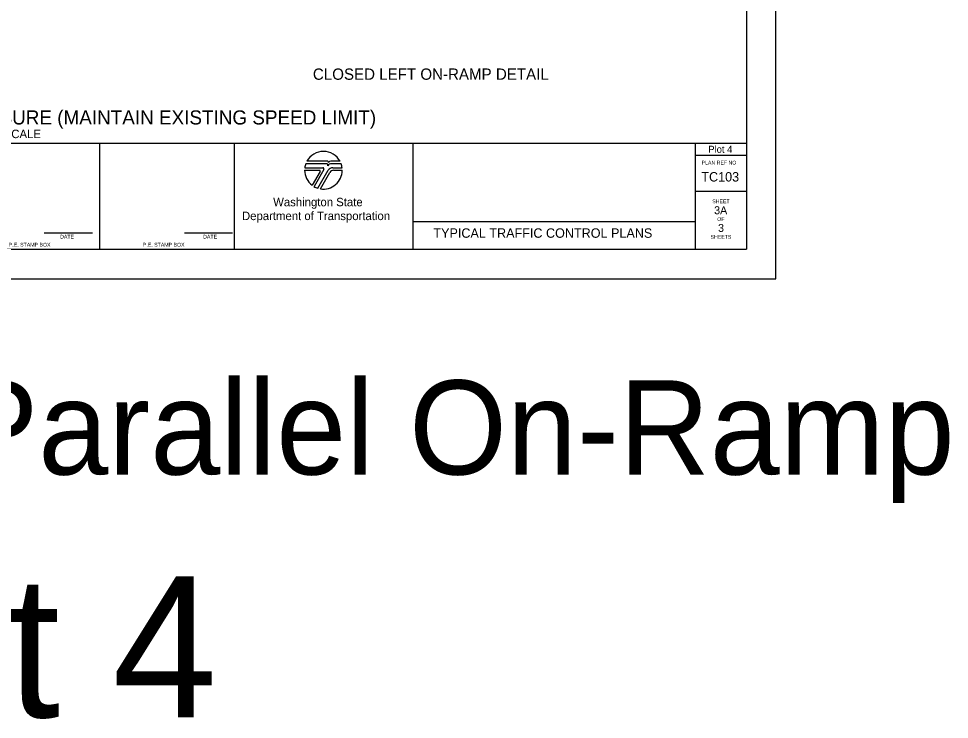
# Model space of a CAD drawing. Extents: x 99999 to 100116, y 99995 to 100013.
# Drawn here: x 100068.02 to 100077.91, y 99995.01 to 100002.45 of the extents above; entities that cross this region are included whole.
import ezdxf

# ---------------------------------------------------------------- set-up
doc = ezdxf.new("R2010")
doc.units = 0
for name, color, linetype in [('SH_DE_DetailHeading1Text', 7, 'Continuous'), ('SH_DE_DetailHeading2Text', 7, 'Continuous'), ('SH_GI_PlotLimits', 7, 'Continuous'), ('SH_GI_SheetBorder', 7, 'Continuous'), ('SH_GI_SheetLocationText', 7, 'Continuous'), ('SH_GI_SheetTextInCells', 7, 'Continuous'), ('SH_GI_TitleBlockText', 7, 'Continuous'), ('SH_GI_WSDOTLogo', 7, 'Continuous')]:
    doc.layers.add(name, color=color, linetype=linetype)

msp = doc.modelspace()

# ---------------------------------------------------------------- linework, layer by layer
at = {"layer": 'SH_GI_PlotLimits'}
msp.add_lwpolyline([(100059.0625, 99999.6875), (100076.0625, 99999.6875), (100076.0625, 100010.6875), (100059.0625, 100010.6875)], close=True, dxfattribs=at)
at = {"layer": 'SH_GI_SheetBorder'}
for p, q in [((100075.75, 100010.375), (100075.75, 100000)), ((100060, 100001.1259), (100075.75, 100001.1259)), ((100068.8828, 100000), (100068.8828, 100001.1259)), ((100070.3089, 100001.1259), (100070.3089, 100000)), ((100072.2055, 100001.1259), (100072.2055, 100000)), ((100075.2079, 100001.1259), (100075.2079, 100000)), ((100075.2079, 100001.0008), (100075.75, 100001.0008)), ((100075.2079, 100000.6176), (100075.75, 100000.6176)), ((100072.2055, 100000.2955), (100075.2079, 100000.2955)), ((100068.2903, 100000.1733), (100068.802, 100000.1733)), ((100069.7797, 100000.1733), (100070.2914, 100000.1733)), ((100060, 100000), (100075.75, 100000))]:
    msp.add_line(p, q, dxfattribs=at)
at = {"layer": 'SH_GI_WSDOTLogo'}
for p, q in [((100071.059, 100000.8661), (100071.2496, 100000.8661)), ((100071.2894, 100000.9094), (100071.0697, 100000.9094)), ((100071.303, 100000.9354), (100071.0815, 100000.9354)), ((100071.433, 100000.9354), (100071.3351, 100000.9354)), ((100071.343, 100000.9094), (100071.3429, 100000.9094)), ((100071.4448, 100000.9094), (100071.343, 100000.9094)), ((100071.3558, 100000.8661), (100071.4555, 100000.8661)), ((100071.0572, 100000.84), (100071.2148, 100000.84)), ((100071.222, 100000.8277), (100071.1364, 100000.6807)), ((100071.261, 100000.8464), (100071.1567, 100000.6672)), ((100071.1989, 100000.6487), (100071.3089, 100000.839)), ((100071.2244, 100000.6428), (100071.3242, 100000.8156)), ((100071.3655, 100000.8394), (100071.4572, 100000.8394))]:
    msp.add_line(p, q, dxfattribs=at)
for centre, radius, start, end in [((100071.2572, 100000.84), 0.2, 28.47865, 151.53204), ((100071.2572, 100000.84), 0.2, 159.69598, 172.50569), ((100071.2497, 100000.853), 0.0131, 329.76834, 90), ((100071.2894, 100000.8946), 0.0148, 327.8418, 89.99855), ((100071.3429, 100000.861), 0.0484, 89.99529, 147.82376), ((100071.303, 100000.9263), 0.00903, 329.87418, 90.00328), ((100071.3558, 100000.8119), 0.0542, 90, 149.99738), ((100071.3352, 100000.9066), 0.0287, 90.00721, 148.16763), ((100071.2572, 100000.84), 0.2, 7.49431, 20.29406), ((100071.2572, 100000.84), 0.2, 179.99864, 232.84327), ((100071.2149, 100000.8318), 0.0082, 329.74356, 90), ((100071.2572, 100000.84), 0.2, 260.54554, 359.80857), ((100071.3654, 100000.7918), 0.0476, 90, 150.05432), ((100071.2572, 100000.84), 0.2, 239.79292, 253.0448)]:
    msp.add_arc(centre, radius, start, end, dxfattribs=at)

# ---------------------------------------------------------------- texts
at = {"layer": 'SH_DE_DetailHeading1Text'}
for s, height, p in [('FREEWAY (2+ LANES): SINGLE LEFT LANE CLOSURE (MAINTAIN EXISTING SPEED LIMIT)', 0.15, (100063.2512, 100001.3259)), ('NOT TO SCALE', 0.09, (100067.3727, 100001.1809))]:
    msp.add_text(s, height=height, rotation=360, dxfattribs=at).set_placement(p)
at = {"layer": 'SH_DE_DetailHeading2Text'}
msp.add_text('CLOSED LEFT ON-RAMP DETAIL', height=0.12, rotation=360, dxfattribs=at).set_placement((100071.1451, 100001.8009))
at = {"layer": 'SH_GI_SheetBorder'}
msp.add_text('PLAN REF NO', height=0.040032, dxfattribs=at).set_placement((100075.2747, 100000.9008))
at = {"layer": 'SH_GI_SheetLocationText'}
for s, height, p in [('Plot 4', 0.075, (100075.3454, 100001.025)), ('Left Ramps: Parallel On-Ramp', 1, (100059.7551, 99997.6071)), ('Plot 4', 1.5, (100065.0007, 99995.0267))]:
    msp.add_text(s, height=height, dxfattribs=at).set_placement(p)
at = {"layer": 'SH_GI_SheetTextInCells'}
for s, height, p in [('Washington State', 0.090072, (100070.7229, 100000.4571)), ('SHEET', 0.04003, (100075.3877, 100000.4896)), ('Department of Transportation', 0.090072, (100070.3916, 100000.3101)), ('OF', 0.04003, (100075.4406, 100000.3008)), ('P.E. STAMP BOX', 0.040032, (100067.915, 100000.0286)), ('DATE', 0.04003, (100068.4597, 100000.1141)), ('P.E. STAMP BOX', 0.040032, (100069.339, 100000.0286)), ('DATE', 0.04003, (100069.9794, 100000.1141)), ('SHEETS', 0.04003, (100075.3698, 100000.112))]:
    msp.add_text(s, height=height, dxfattribs=at).set_placement(p)
at = {"layer": 'SH_GI_TitleBlockText'}
for s, height, p in [('TC103', 0.1, (100075.2718, 100000.72)), ('3A', 0.085, (100075.4076, 100000.3723)), ('3', 0.085, (100075.4493, 100000.1843)), ('TYPICAL TRAFFIC CONTROL PLANS', 0.1, (100072.4251, 100000.1224))]:
    msp.add_text(s, height=height, dxfattribs=at).set_placement(p)

doc.saveas('drawing.dxf')
